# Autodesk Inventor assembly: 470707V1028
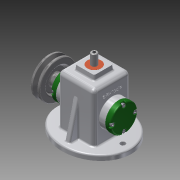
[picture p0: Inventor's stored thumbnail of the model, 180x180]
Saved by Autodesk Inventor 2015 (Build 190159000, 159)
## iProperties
Created: 2017-07
Part Number: 470707V1028
Document SubType Name: Assembly
Designer: Administrator
Author: Administrator
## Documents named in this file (16)
- C:\Users\Administrator\Desktop\470707V1028\470707V1028.iam
- C:\Users\Administrator\Desktop\470707V1028\V벨트풀리.ipt
- C:\Users\Administrator\Desktop\470707V1028\고정핀 1.2 x  8.ipt
- C:\Users\Administrator\Desktop\470707V1028\뒤커버.ipt
- C:\Users\Administrator\Desktop\470707V1028\링크.ipt
- C:\Users\Administrator\Desktop\470707V1028\멈춤나사 M3x8.ipt
- C:\Users\Administrator\Desktop\470707V1028\베어링 12 x 32 x 10.ipt
- C:\Users\Administrator\Desktop\470707V1028\본체.ipt
- C:\Users\Administrator\Desktop\470707V1028\볼트 M4 x 12.ipt
- C:\Users\Administrator\Desktop\470707V1028\부시.ipt
- C:\Users\Administrator\Desktop\470707V1028\슬라이드.ipt
- C:\Users\Administrator\Desktop\470707V1028\앞커버.ipt
- C:\Users\Administrator\Desktop\470707V1028\오일실 12 25 7.ipt
- C:\Users\Administrator\Desktop\470707V1028\키 4 x 4 x 10.ipt
- C:\Users\Administrator\Desktop\470707V1028\편심축.ipt
- C:\Users\Administrator\Desktop\470707V1028\핀 5 x 18.ipt
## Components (3 placed, 3 different names)
1. V벨트풀리:1
2. 고정핀 1.2 x  8:1 — 플러쉬:3
3. 핀 5 x 18:1
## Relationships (1: Flush 1)
- 플러쉬:3 [Flush]: 고정핀 1.2 x  8:1
